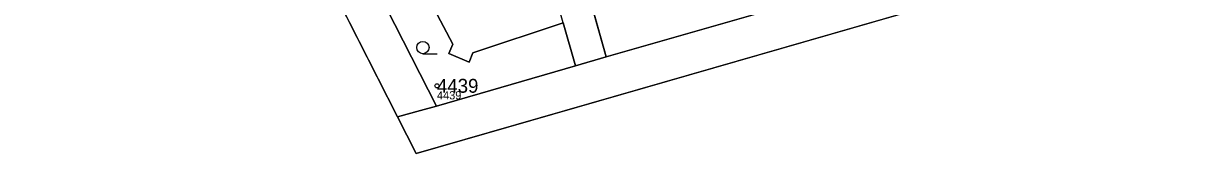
# Model space of a CAD drawing. Extents: x -690132 to -685994, y -975441 to -972444.
# Drawn here: x -689531.2 to -689387.2, y -974887.9 to -974872.1 of the extents above; entities that cross this region are included whole.
import ezdxf

# ---------------------------------------------------------------- set-up
doc = ezdxf.new("R2010")
doc.units = 0
for name, color, linetype in [('Definiční body', 7, 'Continuous'), ('Hranice parcel', 7, 'Continuous'), ('Parcelní čísla', 7, 'Continuous'), ('Polygon budovy', 7, 'Continuous'), ('Polygon ku', 7, 'Continuous'), ('Polygon parcely', 7, 'Continuous'), ('Značky kultur', 7, 'Continuous')]:
    doc.layers.add(name, color=color, linetype=linetype)

msp = doc.modelspace()

# ---------------------------------------------------------------- linework, layer by layer
at = {"layer": 'Definiční body'}
msp.add_circle((-689480.68, -974879.67), 0.25, dxfattribs=at)
at = {"layer": 'Hranice parcel'}
for p, q in [((-689284.97, -974830.8), (-689483.22, -974887.94)), ((-689469.92, -974841), (-689460.02, -974876.12)), ((-689496.01, -974852.14), (-689480.73, -974882.14)), ((-689485.49, -974883.46), (-689500.76, -974853.38)), ((-689460.02, -974876.12), (-689441.78, -974870.91)), ((-689463.76, -974877.21), (-689460.02, -974876.12)), ((-689480.73, -974882.14), (-689463.76, -974877.21)), ((-689483.22, -974887.94), (-689485.49, -974883.46))]:
    msp.add_line(p, q, dxfattribs=at)
for points in [[(-689463.76, -974877.21), (-689465.26, -974871.98), (-689476.31, -974875.63), (-689476.77, -974876.78), (-689479.22, -974875.72), (-689478.76, -974874.57), (-689484.09, -974864.44), (-689491.57, -974850.24)], [(-689485.49, -974883.46), (-689482.69, -974882.68), (-689480.73, -974882.14)]]:
    msp.add_lwpolyline(points, dxfattribs=at)
at = {"layer": 'Polygon budovy'}
msp.add_lwpolyline([(-689484.09, -974864.44), (-689478.76, -974874.57), (-689479.22, -974875.72), (-689476.77, -974876.78), (-689476.31, -974875.63), (-689465.26, -974871.98), (-689468.41, -974861.05), (-689475.12, -974862.98), (-689476.38, -974860.39)], close=True, dxfattribs=at)
at = {"layer": 'Polygon ku'}
msp.add_lwpolyline([(-689531.19, -974866.01), (-689505.57, -974854.63), (-689503.74, -974854.16), (-689500.76, -974853.38), (-689485.49, -974883.46), (-689483.22, -974887.94), (-689284.97, -974830.8)], dxfattribs=at)
at = {"layer": 'Polygon parcely'}
for points in [[(-689374.14, -974851.48), (-689392.8, -974856.95), (-689396.55, -974858.01), (-689414.44, -974863.08), (-689419.29, -974864.47), (-689438.01, -974869.83), (-689441.78, -974870.91), (-689460.02, -974876.12), (-689463.76, -974877.21), (-689480.73, -974882.14), (-689482.69, -974882.68), (-689485.49, -974883.46), (-689483.22, -974887.94), (-689284.97, -974830.8)], [(-689500.76, -974853.38), (-689485.49, -974883.46), (-689482.69, -974882.68), (-689480.73, -974882.14), (-689496.01, -974852.14)]]:
    msp.add_lwpolyline(points, dxfattribs=at)
for points in [[(-689441.78, -974870.91), (-689443.21, -974865.96), (-689447.84, -974867.28), (-689447.8, -974867.42), (-689457.61, -974870.21), (-689460.6, -974859.63), (-689462.77, -974851.91), (-689444.66, -974846.74), (-689448.79, -974832.38), (-689469.92, -974841), (-689460.02, -974876.12)], [(-689469.92, -974841), (-689491.57, -974850.24), (-689484.09, -974864.44), (-689478.76, -974874.57), (-689479.22, -974875.72), (-689476.77, -974876.78), (-689476.31, -974875.63), (-689465.26, -974871.98), (-689463.76, -974877.21), (-689460.02, -974876.12)], [(-689478.76, -974874.57), (-689484.09, -974864.44), (-689491.57, -974850.24), (-689495.73, -974852.02), (-689496.01, -974852.14), (-689480.73, -974882.14), (-689463.76, -974877.21), (-689465.26, -974871.98), (-689476.31, -974875.63), (-689476.77, -974876.78), (-689479.22, -974875.72)]]:
    msp.add_lwpolyline(points, close=True, dxfattribs=at)
at = {"layer": 'Značky kultur'}
msp.add_line((-689482.4, -974875.74), (-689480.65, -974875.74), dxfattribs=at)
msp.add_circle((-689482.4, -974874.99), 0.75, dxfattribs=at)

# ---------------------------------------------------------------- texts
at = {"layer": 'Definiční body'}
msp.add_text('4439', height=1, dxfattribs=at).set_placement((-689480.68, -974881.33))
at = {"layer": 'Parcelní čísla'}
msp.add_text('4439', height=1.7, dxfattribs=at).set_placement((-689480.68, -974880.52))

doc.saveas('drawing.dxf')
